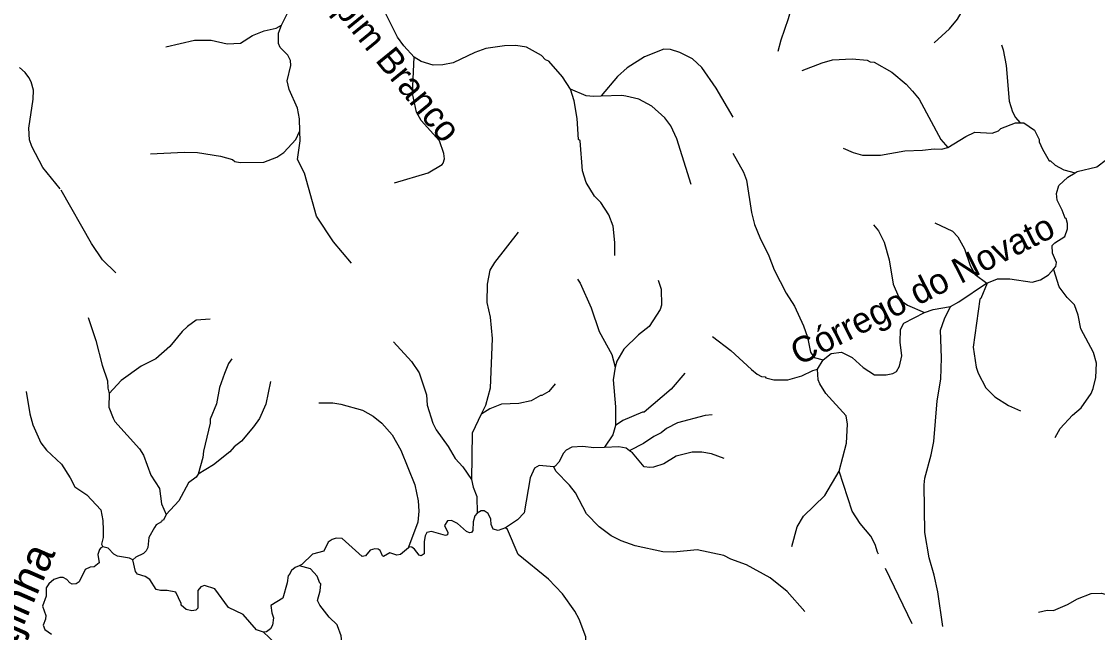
# Model space of a CAD drawing. Extents: x 393 to 446.6, y 8175.5 to 8231.
# Drawn here: x 430.1 to 436.82, y 8184.16 to 8187.97 of the extents above; entities that cross this region are included whole.
import ezdxf
from ezdxf.enums import TextEntityAlignment as Align

# ---------------------------------------------------------------- set-up
doc = ezdxf.new("R2010")
doc.units = 0
doc.header["$LTSCALE"] = 0.064
doc.linetypes.add('LONG_DASHED', pattern=[7.5, 6, -1.5])
doc.layers.add('61', color=7, linetype='Continuous')
doc.layers.add('7', color=7, linetype='Continuous', lineweight=25)
doc.layers.add('9', color=7, linetype='LONG_DASHED', lineweight=25)

msp = doc.modelspace()

# ---------------------------------------------------------------- linework, layer by layer
at = {"layer": '7'}
msp.add_lwpolyline([(435.7989, 8187.8403), (435.895, 8187.9275), (435.945, 8187.9889), (435.9676, 8188.0277), (435.9838, 8188.0712), (435.9934, 8188.2118), (436.0031, 8188.2634), (435.9983, 8188.3022), (435.9434, 8188.4443), (435.9531, 8188.5412), (435.9531, 8188.6058), (435.9208, 8188.735), (435.9304, 8188.8964), (435.9304, 8188.9998), (435.9256, 8189.0256), (435.8982, 8189.0773), (435.832, 8189.1419), (435.7706, 8189.221)], dxfattribs=at)
at = {"layer": '9'}
msp.add_line((435.0709, 8185.8034), (435.1058, 8185.8627), dxfattribs=at)
for points in [[(434.8254, 8187.7883), (434.8437, 8187.8598), (434.8906, 8187.9922), (434.9244, 8188.1181), (434.9774, 8188.2714), (434.9729, 8188.2763), (434.9923, 8188.3119), (435.0116, 8188.4023), (435.0214, 8188.4976), (434.9858, 8188.6639), (434.9325, 8188.7705), (434.9341, 8188.8448), (434.926, 8188.961), (434.9131, 8189.0256), (434.8776, 8189.1257), (434.7749, 8189.3437)], [(431.7242, 8187.9501), (431.795, 8188.0923), (431.8434, 8188.2279), (431.9128, 8188.391), (431.9287, 8188.4621)], [(432.5526, 8187.7523), (432.4884, 8187.8223), (432.4487, 8187.8771), (432.3537, 8188.068), (432.231, 8188.1956), (432.1535, 8188.2957), (432.0889, 8188.349), (431.9468, 8188.4475), (431.9287, 8188.4621)], [(431.0016, 8187.815), (431.1814, 8187.8565), (431.2847, 8187.8565), (431.3864, 8187.8339), (431.4688, 8187.8387), (431.5431, 8187.8872), (431.6174, 8187.9162), (431.6917, 8187.9324), (431.7242, 8187.9501)], [(431.8384, 8187.289), (431.8361, 8187.3659), (431.824, 8187.4334), (431.7724, 8187.5497), (431.7595, 8187.603), (431.782, 8187.6983), (431.7804, 8187.7306), (431.7643, 8187.7645), (431.7158, 8187.8113), (431.7061, 8187.8371), (431.7061, 8187.9017), (431.7242, 8187.9501)], [(433.528, 8187.5516), (433.4789, 8187.6286), (433.3937, 8187.7254), (433.3726, 8187.7354), (433.3484, 8187.7612), (433.2531, 8187.8145), (433.187, 8187.8242), (433.1159, 8187.8226), (432.9996, 8187.8064), (432.9318, 8187.7806), (432.7962, 8187.716), (432.7316, 8187.7031), (432.6718, 8187.7015), (432.5975, 8187.7241), (432.5526, 8187.7523)], [(436.2184, 8187.829), (436.23, 8187.7963), (436.2477, 8187.6983), (436.268, 8187.477), (436.2873, 8187.4108), (436.3067, 8187.3753), (436.334, 8187.3444), (436.3361, 8187.342)], [(434.5445, 8187.3763), (434.4384, 8187.5578), (434.3496, 8187.687), (434.2898, 8187.7419), (434.2123, 8187.7806), (434.1526, 8187.7984), (434.1106, 8187.8016), (433.9911, 8187.7531), (433.8829, 8187.6854), (433.8231, 8187.6305), (433.7195, 8187.5099), (433.7179, 8187.508)], [(432.4302, 8186.9661), (432.6412, 8187.0297), (432.7267, 8187.0814), (432.7348, 8187.0895), (432.7412, 8187.1169), (432.738, 8187.1508), (432.7106, 8187.23), (432.5975, 8187.3559), (432.5668, 8187.4076), (432.5426, 8187.5239), (432.5526, 8187.7523)], [(434.976, 8187.6685), (435.0989, 8187.716), (435.1635, 8187.7338), (435.2862, 8187.7419), (435.3798, 8187.7322), (435.3992, 8187.7224), (435.425, 8187.7208), (435.5348, 8187.6579), (435.6253, 8187.582), (435.664, 8187.5384), (435.706, 8187.4883), (435.84, 8187.238), (435.885, 8187.1879)], [(430.6898, 8186.405), (430.6081, 8186.4872), (430.5387, 8186.5873), (430.3433, 8186.9296), (430.2351, 8187.062), (430.1656, 8187.1945), (430.1511, 8187.2348), (430.1463, 8187.3075), (430.1753, 8187.4883), (430.177, 8187.5449), (430.1624, 8187.5965), (430.1479, 8187.624), (430.1236, 8187.6563), (430.0898, 8187.687)], [(433.8052, 8186.5139), (433.8054, 8186.5938), (433.7941, 8186.6971), (433.7683, 8186.7682), (433.7182, 8186.844), (433.6794, 8186.8844), (433.6262, 8186.9684), (433.6035, 8187.0427), (433.589, 8187.23), (433.5793, 8187.238), (433.5712, 8187.3689), (433.5519, 8187.4787), (433.528, 8187.5516)], [(433.7179, 8187.508), (433.6716, 8187.5064), (433.6261, 8187.5099), (433.528, 8187.5516)], [(434.282, 8186.9563), (434.193, 8187.2413), (434.1542, 8187.3236), (434.1171, 8187.3721), (434.0363, 8187.4463), (433.9556, 8187.4899), (433.8749, 8187.5077), (433.849, 8187.5125), (433.7179, 8187.508)], [(430.9078, 8187.1479), (431.1168, 8187.1589), (431.2008, 8187.1557), (431.3429, 8187.1331), (431.4187, 8187.1121), (431.4333, 8187.0991), (431.4672, 8187.0943), (431.6141, 8187.0959), (431.6965, 8187.1266), (431.7401, 8187.1573), (431.8143, 8187.238), (431.8373, 8187.2866), (431.8384, 8187.289)], [(432.162, 8186.4659), (432.0485, 8186.5986), (431.9435, 8186.7585), (431.8676, 8187.0281), (431.8241, 8187.1121), (431.8402, 8187.23), (431.8384, 8187.289)], [(435.885, 8187.1879), (435.9967, 8187.2558), (436.0532, 8187.2833), (436.1614, 8187.2768), (436.2001, 8187.2913), (436.2147, 8187.3059), (436.306, 8187.342), (436.3361, 8187.342)], [(436.3361, 8187.342), (436.3597, 8187.342), (436.4251, 8187.2966), (436.4553, 8187.2364), (436.4553, 8187.2235), (436.4763, 8187.1767), (436.5166, 8187.104), (436.5247, 8187.104), (436.5538, 8187.0766), (436.6076, 8187.0488), (436.6783, 8187.0289)], [(434.5426, 8187.1524), (434.609, 8187.0337), (434.6273, 8186.9845), (434.658, 8186.7811), (434.6774, 8186.7068), (434.7101, 8186.625), (434.766, 8186.5121), (434.8001, 8186.4242), (434.876, 8186.2789), (434.9277, 8186.1965), (434.9842, 8186.0738), (435.0084, 8186.0027), (435.0262, 8185.9091), (435.0505, 8185.877), (435.1058, 8185.8627)], [(435.2311, 8187.1843), (435.2926, 8187.1557), (435.3524, 8187.1396), (435.4638, 8187.1395), (435.6156, 8187.167), (435.7254, 8187.1702), (435.7997, 8187.1799), (435.8449, 8187.1766), (435.885, 8187.1879)], [(436.6783, 8187.0289), (436.6924, 8187.0375), (436.8147, 8187.0665), (436.8753, 8187.1125)], [(436.5441, 8186.428), (436.5594, 8186.4451), (436.5629, 8186.4695), (436.5384, 8186.5277), (436.5361, 8186.5754), (436.5524, 8186.5917), (436.6153, 8186.6319), (436.6305, 8186.6796), (436.6305, 8186.7134), (436.6223, 8186.7436), (436.6168, 8186.7455), (436.599, 8186.7956), (436.5667, 8186.8586), (436.5634, 8186.9006), (436.578, 8186.9506), (436.6345, 8187.0023), (436.6783, 8187.0289)], [(435.4202, 8186.7047), (435.4506, 8186.6673), (435.4864, 8186.597), (435.5187, 8186.4872), (435.5429, 8186.3354), (435.577, 8186.2569), (435.5981, 8186.2278), (435.6331, 8186.2033), (435.7394, 8186.1578)], [(435.8027, 8186.7179), (435.9133, 8186.6644), (435.9466, 8186.6309), (435.9886, 8186.555), (436.0241, 8186.45), (436.0553, 8186.3951), (436.1278, 8186.3412)], [(433.2027, 8186.6584), (433.0548, 8186.4699), (433.0257, 8186.4222), (433.0093, 8186.3354), (433.0061, 8186.2191), (433.027, 8186.1287), (433.04, 8185.9963), (433.027, 8185.6862), (432.998, 8185.5764), (432.972, 8185.5229)], [(436.1278, 8186.3412), (436.1937, 8186.3684), (436.2712, 8186.3677), (436.4101, 8186.3466), (436.4634, 8186.3612), (436.5118, 8186.3919), (436.5441, 8186.428)], [(436.5539, 8185.3769), (436.5861, 8185.4327), (436.662, 8185.5167), (436.7169, 8185.5619), (436.7782, 8185.6523), (436.7911, 8185.683), (436.8073, 8185.7524), (436.8121, 8185.8413), (436.7944, 8185.9075), (436.7137, 8186.056), (436.6975, 8186.1416), (436.6749, 8186.2046), (436.6297, 8186.2514), (436.5796, 8186.3176), (436.5454, 8186.4241), (436.5441, 8186.428)], [(433.5717, 8186.3649), (433.5892, 8186.3404), (433.6568, 8186.1868), (433.7085, 8186.0383), (433.786, 8185.8962), (433.8067, 8185.8174)], [(434.0768, 8186.3587), (434.0944, 8186.3031), (434.0961, 8186.203), (434.088, 8186.1771), (434.0202, 8186.0706), (433.954, 8186.0173), (433.8619, 8185.9284), (433.8183, 8185.8541), (433.8067, 8185.8174)], [(435.9014, 8186.1956), (435.9526, 8186.2235), (436.1262, 8186.3405), (436.1278, 8186.3412)], [(436.1278, 8186.3412), (436.1291, 8186.3402), (436.0903, 8186.2449), (436.0839, 8186.2401), (436.0435, 8185.9414), (436.0613, 8185.8154), (436.0734, 8185.7779), (436.1226, 8185.6878), (436.1776, 8185.6313), (436.2631, 8185.5764), (436.3382, 8185.5436)], [(435.1058, 8185.8627), (435.1559, 8185.9011), (435.22, 8185.9107), (435.2878, 8185.8768), (435.3556, 8185.8138), (435.4267, 8185.7686), (435.4993, 8185.7685), (435.5413, 8185.7766), (435.5639, 8185.7895), (435.5833, 8185.8235), (435.5962, 8185.8865), (435.5865, 8185.972), (435.5881, 8186.0512), (435.6107, 8186.0915), (435.7394, 8186.1578)], [(435.8529, 8184.1974), (435.8223, 8184.4138), (435.7997, 8184.5187), (435.7674, 8184.6269), (435.7399, 8184.7852), (435.7367, 8185.0823), (435.7399, 8185.1243), (435.7803, 8185.2696), (435.7965, 8185.352), (435.8174, 8185.6055), (435.8417, 8185.7411), (435.8449, 8185.8752), (435.8385, 8186.0463), (435.8642, 8186.119), (435.9014, 8186.1956)], [(435.7394, 8186.1578), (435.7918, 8186.1764), (435.9014, 8186.1956)], [(430.5182, 8186.1272), (430.5645, 8185.9834), (430.6049, 8185.8283), (430.6388, 8185.7315), (430.6404, 8185.6862), (430.6485, 8185.6523)], [(431.2803, 8186.115), (431.1927, 8186.1093), (431.1378, 8186.0705), (431.1039, 8186.0398), (431.028, 8185.9462), (430.9408, 8185.8687), (430.8487, 8185.8235), (430.7228, 8185.733), (430.6485, 8185.6523)], [(434.4157, 8186.0085), (434.5305, 8185.9204), (434.658, 8185.8009), (434.6951, 8185.7734), (434.721, 8185.7589), (434.7436, 8185.7556), (434.7484, 8185.7492), (434.7985, 8185.7363), (434.8857, 8185.7379), (434.9719, 8185.7618), (435.0406, 8185.7955), (435.0709, 8185.8034)], [(432.4237, 8185.9741), (432.5362, 8185.8525), (432.5846, 8185.7815), (432.6298, 8185.6443), (432.6347, 8185.5797), (432.6686, 8185.4666), (432.6896, 8185.4246), (432.7655, 8185.3213), (432.8091, 8185.2454), (432.8575, 8185.1953), (432.9116, 8185.1156)], [(431.4143, 8185.868), (431.3945, 8185.8396), (431.3687, 8185.7767), (431.338, 8185.6895), (431.3186, 8185.5877), (431.2798, 8185.4925), (431.2798, 8185.4666), (431.2379, 8185.2922), (431.2331, 8185.2518), (431.2037, 8185.1482)], [(433.8067, 8185.8174), (433.7941, 8185.7363), (433.8103, 8185.5683), (433.8097, 8185.4529)], [(434.2434, 8185.7795), (434.1574, 8185.6798), (433.9895, 8185.536), (433.9782, 8185.536), (433.8555, 8185.4827), (433.8097, 8185.4529)], [(435.2057, 8185.1674), (435.2523, 8185.3423), (435.2587, 8185.4602), (435.2507, 8185.5134), (435.1231, 8185.6523), (435.0843, 8185.7121), (435.0746, 8185.7379), (435.0709, 8185.8034)], [(431.6561, 8185.7267), (431.6271, 8185.5845), (431.5867, 8185.4957), (431.5495, 8185.444), (431.4752, 8185.3536), (431.4301, 8185.3196), (431.4026, 8185.2874), (431.3008, 8185.2066), (431.2037, 8185.1482)], [(433.4332, 8185.713), (433.3925, 8185.6653), (433.3507, 8185.6386), (433.3419, 8185.6394), (433.2838, 8185.6071), (433.2063, 8185.5893), (433.0981, 8185.5861), (433.0255, 8185.557), (432.9747, 8185.5246), (432.972, 8185.5229)], [(430.1312, 8185.664), (430.1543, 8185.5248), (430.1721, 8185.4569), (430.2222, 8185.3439), (430.2577, 8185.2987), (430.3514, 8185.2099), (430.4063, 8185.1259), (430.4353, 8185.0694), (430.5096, 8185.0193), (430.5968, 8184.9257), (430.6097, 8184.8595), (430.6106, 8184.7991), (430.6113, 8184.7529), (430.6016, 8184.7109), (430.6089, 8184.695)], [(430.6485, 8185.6523), (430.646, 8185.5665), (430.6727, 8185.4989), (430.684, 8185.4779), (430.8374, 8185.3067), (430.8632, 8185.2664), (430.9084, 8185.142), (430.9634, 8185.0581), (430.9746, 8184.9628), (431.0053, 8184.8966)], [(431.958, 8185.594), (432.0453, 8185.5942), (432.0954, 8185.5861), (432.2294, 8185.5473), (432.2972, 8185.5102), (432.3505, 8185.4666), (432.4151, 8185.3939), (432.4699, 8185.2987), (432.5571, 8185.0823), (432.5781, 8184.9822), (432.5814, 8184.9176), (432.5766, 8184.8481), (432.5182, 8184.6926), (432.5168, 8184.6888)], [(432.972, 8185.5229), (432.914, 8185.4036), (432.9116, 8185.1156)], [(434.4128, 8185.5185), (434.3686, 8185.515), (434.1962, 8185.4699), (434.1284, 8185.4343), (434.0944, 8185.4069), (434.0492, 8185.3842), (433.9846, 8185.3406), (433.9001, 8185.2963), (433.8973, 8185.2948)], [(433.8097, 8185.4529), (433.7934, 8185.3936), (433.7418, 8185.3167), (433.7413, 8185.3159)], [(433.7413, 8185.3159), (433.6743, 8185.3132), (433.6068, 8185.3213), (433.5374, 8185.3164), (433.5018, 8185.2986), (433.4857, 8185.2793), (433.4566, 8185.2228), (433.434, 8185.1985), (433.4243, 8185.1937)], [(433.8973, 8185.2948), (433.8757, 8185.3103), (433.8303, 8185.3196), (433.7413, 8185.3159)], [(434.4891, 8185.2466), (434.4093, 8185.2745), (434.3496, 8185.2857), (434.2882, 8185.2857), (434.1881, 8185.2599), (434.1122, 8185.2131), (434.046, 8185.1921), (434.0234, 8185.1905), (433.9895, 8185.1953), (433.9164, 8185.2812), (433.8973, 8185.2948)], [(433.4243, 8185.1937), (433.3324, 8185.2036), (433.3032, 8185.1861), (433.2774, 8185.1259), (433.2402, 8184.9079), (433.1982, 8184.8627), (433.124, 8184.8126)], [(431.2037, 8185.1482), (431.1909, 8185.1307), (431.1442, 8185.0936), (431.0845, 8184.9822), (431.0053, 8184.8966)], [(434.992, 8184.2916), (434.8808, 8184.417), (434.7759, 8184.5009), (434.6274, 8184.5833), (434.5288, 8184.6188), (434.4853, 8184.6414), (434.3205, 8184.6769), (434.172, 8184.6608), (434.1042, 8184.664), (433.933, 8184.7012), (433.8458, 8184.7319), (433.7828, 8184.7642), (433.7069, 8184.8207), (433.6294, 8184.9014), (433.5599, 8185.0322), (433.5228, 8185.0791), (433.4372, 8185.1678), (433.4243, 8185.1937)], [(434.9096, 8184.6964), (434.9438, 8184.8207), (434.9826, 8184.8853), (435.1166, 8185.0145), (435.2057, 8185.1674)], [(435.6624, 8184.2138), (435.4444, 8184.6625), (435.4315, 8184.7093), (435.404, 8184.7625), (435.3362, 8184.8401), (435.2878, 8184.9176), (435.2057, 8185.1674)], [(432.9116, 8185.1156), (432.921, 8185.0673), (432.9447, 8185.0096), (432.9458, 8184.9061)], [(431.0053, 8184.8966), (430.9876, 8184.861), (430.9779, 8184.8594), (430.9747, 8184.8513), (430.9424, 8184.832), (430.9311, 8184.8158), (430.8971, 8184.7529), (430.89, 8184.6902), (430.8807, 8184.6704), (430.8632, 8184.6529), (430.8143, 8184.6296), (430.7962, 8184.6136)], [(432.9458, 8184.9061), (432.9318, 8184.8875), (432.9213, 8184.8514), (432.919, 8184.7967), (432.9109, 8184.7851), (432.8992, 8184.7828), (432.8794, 8184.7909), (432.8224, 8184.8398), (432.7865, 8184.8594), (432.7607, 8184.8578), (432.7429, 8184.8288), (432.7639, 8184.7852), (432.7616, 8184.7689), (432.7476, 8184.7665), (432.6614, 8184.791), (432.6323, 8184.7852), (432.6207, 8184.7642), (432.616, 8184.7281), (432.616, 8184.6502), (432.5974, 8184.6379), (432.5835, 8184.6437), (432.5555, 8184.681), (432.5392, 8184.6926), (432.5241, 8184.6949), (432.5168, 8184.6888)], [(433.124, 8184.8126), (433.0778, 8184.7964), (433.0464, 8184.8046), (433.0336, 8184.8348), (433.0312, 8184.8686), (433.0138, 8184.9023), (432.9906, 8184.9193), (432.9703, 8184.92), (432.9458, 8184.9061)], [(436.4508, 8184.2877), (436.5037, 8184.2991), (436.5441, 8184.2975), (436.6315, 8184.3342), (436.6943, 8184.3701), (436.7783, 8184.4041), (436.8429, 8184.4057), (436.9333, 8184.3798), (436.9591, 8184.3814), (437.0382, 8184.4235), (437.1206, 8184.438), (437.1626, 8184.4622), (437.1868, 8184.4848), (437.2659, 8184.5865), (437.3192, 8184.6301), (437.366, 8184.7028), (437.3854, 8184.7755), (437.3838, 8184.8562), (437.3888, 8184.8874)], [(433.753, 8183.7474), (433.7461, 8183.7654), (433.7554, 8183.8131), (433.7484, 8183.8282), (433.6855, 8183.8643), (433.6832, 8183.8794), (433.7042, 8183.9132), (433.7065, 8183.9365), (433.7007, 8183.9586), (433.6355, 8184.0161), (433.6274, 8184.0394), (433.625, 8184.1325), (433.5819, 8184.2431), (433.5552, 8184.2926), (433.4783, 8184.4019), (433.3921, 8184.4927), (433.2012, 8184.6469), (433.1349, 8184.8023), (433.124, 8184.8126)], [(432.5168, 8184.6888), (432.467, 8184.6472), (432.4438, 8184.6437), (432.4007, 8184.6576), (432.3623, 8184.6355), (432.3541, 8184.639), (432.3402, 8184.6728), (432.3285, 8184.6809), (432.3076, 8184.6821), (432.2784, 8184.6739), (432.2482, 8184.639), (432.2284, 8184.6344), (432.1039, 8184.746), (432.0667, 8184.7483), (432.0399, 8184.7402), (432.0166, 8184.7239), (431.9898, 8184.6669), (431.9188, 8184.6494), (431.8524, 8184.5837), (431.8347, 8184.5759)], [(430.6089, 8184.695), (430.5972, 8184.6892), (430.5879, 8184.6787), (430.5774, 8184.6473), (430.5856, 8184.5949), (430.5542, 8184.5705), (430.5309, 8184.5682), (430.4994, 8184.553), (430.4611, 8184.4756), (430.4424, 8184.464), (430.418, 8184.4617), (430.4028, 8184.4698), (430.3842, 8184.4919), (430.3621, 8184.5036), (430.34, 8184.5036), (430.304, 8184.4902), (430.2713, 8184.4646), (430.2562, 8184.439), (430.255, 8184.3878), (430.2318, 8184.325), (430.2539, 8184.2673), (430.2516, 8184.2429), (430.2376, 8184.2068), (430.2469, 8184.1789), (430.2888, 8184.1498)], [(430.7962, 8184.6136), (430.7753, 8184.6252), (430.7008, 8184.6374), (430.6787, 8184.6491), (430.6426, 8184.6863), (430.6089, 8184.695)], [(431.6112, 8184.1624), (431.5692, 8184.1775), (431.4854, 8184.2718), (431.3929, 8184.3153), (431.3089, 8184.4331), (431.2449, 8184.4542), (431.2216, 8184.4449), (431.2018, 8184.4216), (431.203, 8184.3117), (431.1902, 8184.3001), (431.1657, 8184.2954), (431.1285, 8184.3047), (431.099, 8184.3298), (431.099, 8184.3411), (431.0651, 8184.4122), (431.0104, 8184.4233), (430.9697, 8184.4221), (430.9417, 8184.4279), (430.9022, 8184.4914), (430.8731, 8184.51), (430.8253, 8184.5251), (430.8137, 8184.5414), (430.7962, 8184.6136)], [(431.8347, 8184.5759), (431.8105, 8184.5651), (431.7872, 8184.5464), (431.7708, 8184.5155), (431.7659, 8184.5155), (431.7595, 8184.4703), (431.732, 8184.375), (431.6577, 8184.3282), (431.6636, 8184.2822), (431.6741, 8184.252), (431.6694, 8184.2054), (431.6554, 8184.1833), (431.631, 8184.1647), (431.6112, 8184.1624)], [(432.3575, 8183.5061), (432.3226, 8183.5864), (432.2391, 8183.6855), (432.1809, 8183.7307), (432.1308, 8183.8034), (432.1098, 8183.8809), (432.1098, 8184.0198), (432.0969, 8184.1393), (432.0752, 8184.2017), (432.0728, 8184.2087), (432.0227, 8184.2555), (431.9645, 8184.3298), (431.9484, 8184.3605), (431.9661, 8184.4202), (431.9694, 8184.4638), (431.9629, 8184.4671), (431.9468, 8184.5123), (431.9048, 8184.5575), (431.8361, 8184.5755), (431.8347, 8184.5759)], [(431.779, 8183.626), (431.7804, 8183.6575), (431.7853, 8183.7695), (431.7756, 8183.897), (431.7595, 8184.0036), (431.7175, 8184.0634), (431.6112, 8184.1624)]]:
    msp.add_lwpolyline(points, dxfattribs=at)

# ---------------------------------------------------------------- texts
at = {"layer": '61'}
for s, height, rotation, p in [('Córrego Capim Branco', 0.16, 309.121, (432.0426, 8188.0543)), ('Córrego do Novato', 0.16, 26.828, (435.7608, 8186.2317)), ('Córrego da Lajinha', 0.2, 66.318, (429.8591, 8183.6171))]:
    msp.add_text(s, height=height, rotation=rotation, dxfattribs=at).set_placement(p, align=Align.CENTER)

doc.saveas('drawing.dxf')
